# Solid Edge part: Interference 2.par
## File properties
Last saved by: Lee
Revision: 59
Accuracy: 0.990
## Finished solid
Body 1: solid body, 4 faces, 4 edges, 0 vertices.
  Faces by surface: cylinder 4
  Edges by curve: intersection 4
Body 2: solid body, 4 faces, 4 edges, 2 vertices.
  Faces by surface: cylinder 3, plane 1
  Edges by curve: intersection 2, circle 1, ellipse 1
Body 3: solid body, 5 faces, 6 edges, 2 vertices.
  Faces by surface: cylinder 4, plane 1
  Edges by curve: intersection 4, circle 1, ellipse 1
Body 4: solid body, 5 faces, 7 edges, 4 vertices.
  Faces by surface: cylinder 4, plane 1
  Edges by curve: intersection 3, circle 2, ellipse 2
Body 5: solid body, 6 faces, 12 edges, 8 vertices.
  Faces by surface: cylinder 4, plane 2
  Edges by curve: circle 4, ellipse 4, intersection 4
Body 6: solid body, 4 faces, 4 edges, 0 vertices.
  Faces by surface: cylinder 4
  Edges by curve: intersection 4
Body 7: solid body, 6 faces, 12 edges, 8 vertices.
  Faces by surface: cylinder 4, plane 2
  Edges by curve: circle 4, ellipse 4, intersection 4
Body 8: solid body, 4 faces, 4 edges, 0 vertices.
  Faces by surface: cylinder 4
  Edges by curve: intersection 4
Bounding box of the edges (mm): 1721.304 x 769.079 x 416.577, from (-809.8183, -383.5428, 214.5108) to (911.4856, 385.5361, 631.0878).
Cylindrical faces by radius (mm): R5 x1, R37 x4, R38.5 x2, R91 x4, R109.5375 x4, R850 x8, R875.4 x8
Planar faces by outward normal: oblique 7
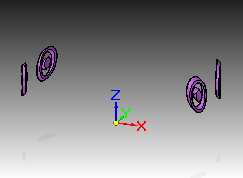
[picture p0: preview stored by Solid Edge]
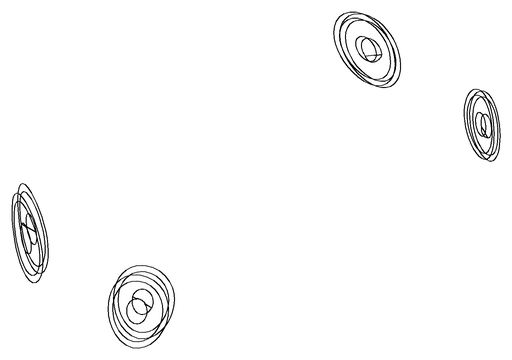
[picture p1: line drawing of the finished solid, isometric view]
